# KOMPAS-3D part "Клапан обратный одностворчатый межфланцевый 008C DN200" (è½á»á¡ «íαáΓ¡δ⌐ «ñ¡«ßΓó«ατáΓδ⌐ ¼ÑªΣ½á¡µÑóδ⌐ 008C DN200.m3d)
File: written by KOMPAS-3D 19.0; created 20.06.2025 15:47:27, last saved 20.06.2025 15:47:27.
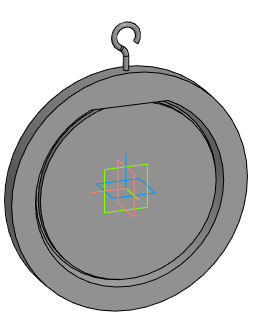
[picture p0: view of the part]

Document properties: Полное имя файла: E:\Dendor Работа Сачек\3D для проектировщиков\5.1 Тип 008C. Клапан обратный одностворчатый межфланцевый\stp_Клапан обратный одностворчатый межфланцевый 008C\Клапан обратный одностворчатый межфланцевый 008C DN200.m3d

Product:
- Part/product: Клапан обратный одностворчатый межфланцевый 008C DN200

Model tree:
1. Операция без истории:1  (labels: Клапан обратный одностворчатый межфланцевый 008C DN200)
